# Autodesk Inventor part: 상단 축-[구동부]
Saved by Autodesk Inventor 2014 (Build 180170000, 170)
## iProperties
Created: 2025-02
Part Number: 상단 축-[구동부]
Material: 강철, 탄소
Document SubType Name: Modeling
Designer: dg
Density: 7.87 g/cm^3
Appearance: 반연마
Mass: 53.8722 g
Surface Area: 29.9371 cm^2
Volume: 6.84526 cm^3
Author: jhkim
Creation Date: 2025-01-06
Sending System: Autodesk Inventor 2025
Preprocessor: ST-DEVELOPER v20
Author: dg
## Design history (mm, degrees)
node "상단 축1"
node "솔리드1"
node "기준1"
